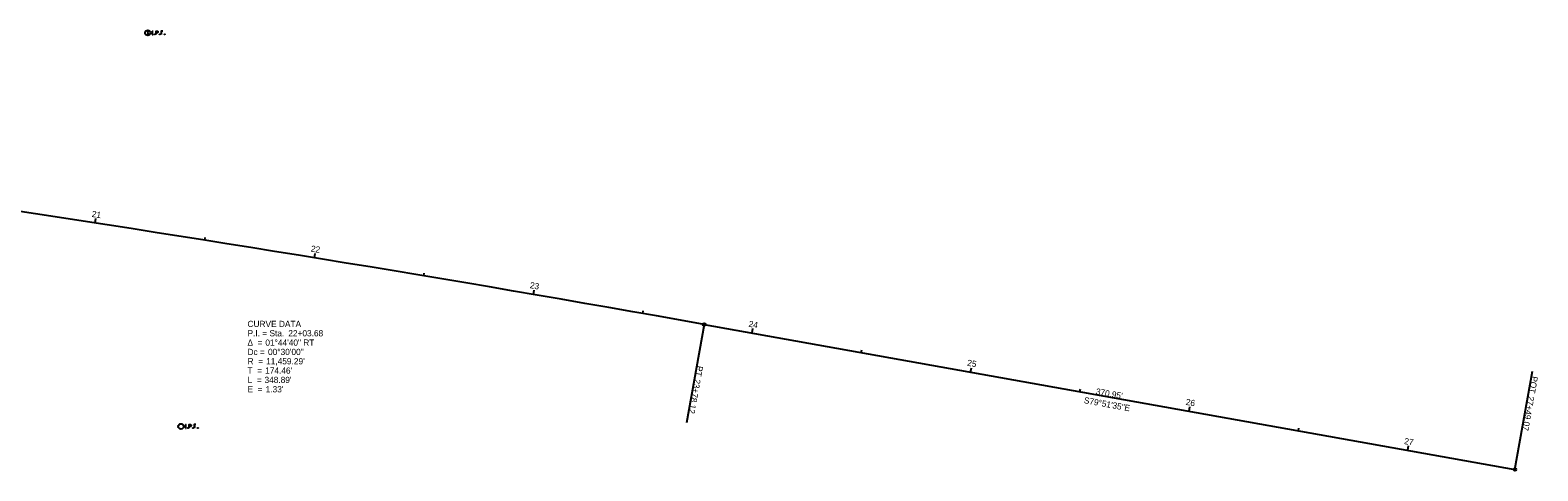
# Model space of a CAD drawing. Extents: x 1918148 to 1920349, y 624677 to 627727.
# Drawn here: x 1919670 to 1920349, y 625652 to 625851 of the extents above; entities that cross this region are included whole.
import ezdxf

# ---------------------------------------------------------------- set-up
doc = ezdxf.new("R2010")
doc.units = 0
for name, color, linetype in [('_CIVIL_CONSTRUCTION', 7, 'Continuous'), ('RS_Raster1', 7, 'Continuous'), ('RW_X_CL', 7, 'Continuous'), ('RW_X_CL_100_Bearings', 7, 'Continuous'), ('RW_X_CL_100_Cardinal_Points', 7, 'Continuous'), ('RW_X_CL_100_Curve_Data', 7, 'Continuous'), ('SV_X_Mon_Cells_Found', 7, 'Continuous')]:
    doc.layers.add(name, color=color, linetype=linetype)

msp = doc.modelspace()

# ---------------------------------------------------------------- linework, layer by layer
at = {"layer": 'RS_Raster1'}
msp.add_line((1919973.5, 625718.31), (1920338.65, 625653), dxfattribs=at)
msp.add_arc((1917955.99, 614438.02), 11459.29, 79.859722, 81.604167, dxfattribs=at)
at = {"layer": 'RW_X_CL'}
for p, q in [((1919973.5, 625718.31), (1919965.58, 625674.02)), ((1920338.65, 625653), (1920346.58, 625697.3))]:
    msp.add_line(p, q, dxfattribs=at)
for centre in [(1919973.5, 625718.31), (1920338.65, 625653)]:
    msp.add_circle(centre, 0.6, dxfattribs=at)
at = {"layer": 'RW_X_CL_100_Cardinal_Points'}
for p, q in [((1919699.16, 625763.95), (1919699.46, 625765.93)), ((1919748.56, 625756.24), (1919748.75, 625757.42)), ((1919797.93, 625748.31), (1919798.25, 625750.28)), ((1919847.26, 625740.16), (1919847.46, 625741.35)), ((1919896.56, 625731.8), (1919896.89, 625733.77)), ((1919945.81, 625723.23), (1919946.02, 625724.41)), ((1919995.04, 625714.46), (1919995.39, 625716.43)), ((1920044.26, 625705.66), (1920044.47, 625706.84)), ((1920093.48, 625696.85), (1920093.83, 625698.82)), ((1920142.7, 625688.05), (1920142.91, 625689.23)), ((1920191.92, 625679.25), (1920192.27, 625681.22)), ((1920241.13, 625670.44), (1920241.35, 625671.63)), ((1920290.35, 625661.64), (1920290.71, 625663.61))]:
    msp.add_line(p, q, dxfattribs=at)
at = {"layer": 'SV_X_Mon_Cells_Found'}
msp.add_line((1919722.89, 625849.69), (1919722.89, 625848.8), dxfattribs=at)
for points in [[(1919724.92, 625850.37), (1919725.27, 625850.37)], [(1919725.09, 625848.77), (1919725.09, 625850.37)], [(1919726.05, 625848.98), (1919726.11, 625848.98), (1919726.14, 625848.96), (1919726.17, 625848.91), (1919726.17, 625848.85), (1919726.14, 625848.8), (1919726.11, 625848.77), (1919726.05, 625848.77), (1919726.02, 625848.8), (1919725.98, 625848.85), (1919725.98, 625848.91), (1919726.02, 625848.96), (1919726.05, 625848.98)], [(1919726.66, 625848.77), (1919726.66, 625850.37), (1919727.19, 625850.37), (1919727.24, 625850.36), (1919727.32, 625850.33), (1919727.35, 625850.31), (1919727.38, 625850.28), (1919727.43, 625850.22), (1919727.46, 625850.16), (1919727.48, 625850.05), (1919727.48, 625849.9), (1919727.47, 625849.85), (1919727.45, 625849.78), (1919727.41, 625849.69), (1919727.36, 625849.65), (1919727.33, 625849.63), (1919727.27, 625849.6), (1919727.19, 625849.59), (1919726.66, 625849.59)], [(1919728.3, 625848.98), (1919728.35, 625848.98), (1919728.39, 625848.96), (1919728.42, 625848.91), (1919728.42, 625848.85), (1919728.39, 625848.8), (1919728.35, 625848.77), (1919728.3, 625848.77), (1919728.27, 625848.8), (1919728.23, 625848.85), (1919728.23, 625848.91), (1919728.27, 625848.96), (1919728.3, 625848.98)], [(1919729.67, 625850.37), (1919728.91, 625850.37), (1919728.91, 625848.77)], [(1919728.91, 625849.59), (1919729.45, 625849.59)], [(1919730.45, 625848.98), (1919730.5, 625848.98), (1919730.54, 625848.96), (1919730.57, 625848.91), (1919730.57, 625848.85), (1919730.54, 625848.8), (1919730.5, 625848.77), (1919730.45, 625848.77), (1919730.42, 625848.8), (1919730.38, 625848.85), (1919730.38, 625848.91), (1919730.42, 625848.96), (1919730.45, 625848.98)], [(1919724.92, 625848.77), (1919725.27, 625848.77)], [(1919739.87, 625673.2), (1919740.22, 625673.2)], [(1919740.05, 625671.6), (1919740.05, 625673.2)], [(1919741.61, 625671.6), (1919741.61, 625673.2), (1919742.14, 625673.2), (1919742.2, 625673.19), (1919742.27, 625673.16), (1919742.31, 625673.14), (1919742.34, 625673.11), (1919742.38, 625673.05), (1919742.42, 625672.99), (1919742.44, 625672.88), (1919742.44, 625672.73), (1919742.43, 625672.68), (1919742.41, 625672.61), (1919742.36, 625672.52), (1919742.32, 625672.48), (1919742.28, 625672.46), (1919742.23, 625672.43), (1919742.14, 625672.42), (1919741.61, 625672.42)], [(1919744.62, 625673.2), (1919743.86, 625673.2), (1919743.86, 625671.6)], [(1919739.87, 625671.6), (1919740.22, 625671.6)], [(1919741.01, 625671.81), (1919741.06, 625671.81), (1919741.09, 625671.79), (1919741.13, 625671.74), (1919741.13, 625671.68), (1919741.09, 625671.63), (1919741.06, 625671.6), (1919741.01, 625671.6), (1919740.97, 625671.63), (1919740.94, 625671.68), (1919740.94, 625671.74), (1919740.97, 625671.79), (1919741.01, 625671.81)], [(1919743.25, 625671.81), (1919743.31, 625671.81), (1919743.34, 625671.79), (1919743.38, 625671.74), (1919743.38, 625671.68), (1919743.34, 625671.63), (1919743.31, 625671.6), (1919743.25, 625671.6), (1919743.22, 625671.63), (1919743.19, 625671.68), (1919743.19, 625671.74), (1919743.22, 625671.79), (1919743.25, 625671.81)], [(1919743.86, 625672.42), (1919744.4, 625672.42)], [(1919745.4, 625671.81), (1919745.46, 625671.81), (1919745.49, 625671.79), (1919745.53, 625671.74), (1919745.53, 625671.68), (1919745.49, 625671.63), (1919745.46, 625671.6), (1919745.4, 625671.6), (1919745.37, 625671.63), (1919745.34, 625671.68), (1919745.34, 625671.74), (1919745.37, 625671.79), (1919745.4, 625671.81)]]:
    msp.add_lwpolyline(points, dxfattribs=at)
for centre, radius in [((1919722.89, 625849.57), 1.2), ((1919722.89, 625850.22), 0.16), ((1919737.86, 625672.4), 1.2)]:
    msp.add_circle(centre, radius, dxfattribs=at)

# ---------------------------------------------------------------- texts
at = {"layer": '_CIVIL_CONSTRUCTION'}
msp.add_text('S79°51\'35"E', height=2.8, rotation=349.85972, dxfattribs=at).set_placement((1920144.33, 625682.88))
at = {"layer": 'RW_X_CL'}
for s, p in [('23+78.12', (1919969.17, 625693.87)), ('PT', (1919970.25, 625699.86)), ('POT', (1920346.24, 625695.18)), ('27+49.07', (1920344.64, 625686.19))]:
    msp.add_text(s, height=2.8, rotation=259.85972, dxfattribs=at).set_placement(p)
at = {"layer": 'RW_X_CL_100_Bearings'}
for s, p in [('CURVE DATA', (1919767.83, 625717.13)), ('P.I. = Sta. ', (1919767.83, 625712.93)), ('22+03.68', (1919786.2, 625712.93)), ('Δ  = ', (1919767.83, 625708.73)), ('Dc = ', (1919767.83, 625704.53)), ('01°44\'40" RT', (1919775.86, 625708.73)), ('00°30\'00"', (1919777.07, 625704.53)), ('R  = ', (1919767.83, 625700.33)), ("11,459.29'", (1919776.2, 625700.33)), ('T  = ', (1919767.83, 625696.13)), ('L  = ', (1919767.83, 625691.93)), ("348.89'", (1919775.48, 625691.93)), ("174.46'", (1919775.77, 625696.13)), ('E  = ', (1919767.83, 625687.73)), ("1.33'", (1919775.99, 625687.73))]:
    msp.add_text(s, height=2.8, dxfattribs=at).set_placement(p)
at = {"layer": 'RW_X_CL_100_Cardinal_Points'}
for s, rotation, p in [('21', 351.25029, (1919697.54, 625766.73)), ('22', 350.75029, (1919796.17, 625751.13)), ('23', 350.2503, (1919894.84, 625734.68)), ('24', 349.85972, (1919993.36, 625717.3)), ('25', 349.85972, (1920091.75, 625699.75)), ('26', 349.85972, (1920190.2, 625682.14)), ('27', 349.85972, (1920288.58, 625664.5))]:
    msp.add_text(s, height=2.8, rotation=rotation, dxfattribs=at).set_placement(p)
at = {"layer": 'RW_X_CL_100_Curve_Data'}
msp.add_text("370.95'", height=2.8, rotation=349.85972, dxfattribs=at).set_placement((1920149.7, 625686.85))

doc.saveas('drawing.dxf')
